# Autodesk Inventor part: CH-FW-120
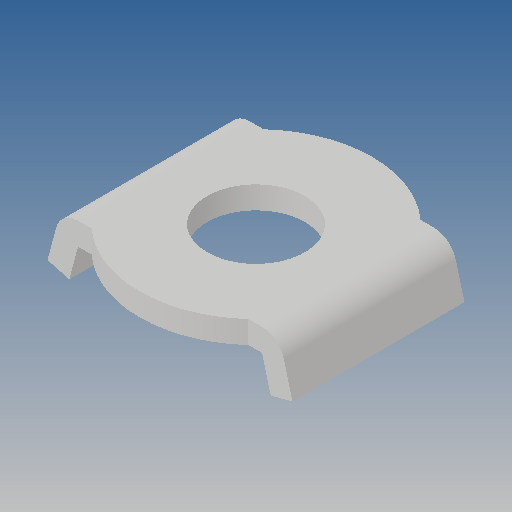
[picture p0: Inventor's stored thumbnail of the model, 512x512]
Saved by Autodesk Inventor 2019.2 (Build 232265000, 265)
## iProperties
Created: 2012-09
Part Number: CH-FW-120
Material: Ogólny
Document SubType Name: Modeling
Designer: CADENGINEERING4
Density: 1 g/cm^3
Appearance: Domyślna
Author: CADENGINEERING4
Revision Number: ÈÎºÎ
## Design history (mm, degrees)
feature "ÇÐ³ý-À­Éì1"
node "Bryła1"
